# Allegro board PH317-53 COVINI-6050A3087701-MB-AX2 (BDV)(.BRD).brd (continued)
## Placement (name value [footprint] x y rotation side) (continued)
C51157  1uF_6.3V_1  [CSC_060X030X039_2]  167.38 85.8 0 top
C51158  1uF_6.3V_1  [CSC_060X030X039_2]  178.08 88.22 90 top
C51159  1uF_6.3V_1  [CSC_060X030X039_2]  173.78 89.84 0 top
C51160  1uF_6.3V_1  [CSC_060X030X039_2]  163.95 89.01 270 bottom
C51161  1uF_6.3V_1  [CSC_060X030X039_2]  177.11 85.77 180 top
C51162  1uF_6.3V_1  [CSC_060X030X039_2]  170.02 87.33 180 top
C51210  10uF_4V_3  [CSC_160X080X090_2]  183.05 85.73 270 top
C51211  10uF_4V_3  [CSC_160X080X090_2]  189.81 100.61 90 top
C51212  10uF_4V_3  [CSC_160X080X090_2]  183 100.53 90 top
C51213  10uF_4V_3  [CSC_160X080X090_2]  186.74 93.45 0 top
C51214  10uF_4V_3  [CSC_160X080X090_2]  190.55 85.55 270 top
C51215  10uF_4V_3  [CSC_160X080X090_2]  193.62 97.36 90 top
C51216  22uF_4V_3  [CSC_160X080X100_2]  188.97 83.56 0 bottom
C51217  22uF_4V_3  [CSC_160X080X100_2]  196.49 90.57 90 bottom
C51218  22uF_4V_3  [CSC_160X080X100_2]  191.89 83.56 180 bottom
C51219  22uF_4V_3  [CSC_160X080X100_2]  196.62 93.6 90 bottom
C51220  22uF_4V_3  [CSC_160X080X100_2]  184.52 83.56 180 bottom
C51221  22uF_4V_3  [CSC_160X080X100_2]  181.6 83.56 0 bottom
C51222  1uF_6.3V_1  [CSC_060X030X039_2]  191.72 85.64 180 top
C51223  1uF_6.3V_1  [CSC_060X030X039_2]  192.68 94.29 90 top
C51224  1uF_6.3V_1  [CSC_060X030X039_2]  187.7 87.33 90 top
C51225  1uF_6.3V_1  [CSC_060X030X039_2]  186.02 98.62 270 top
C51226  1uF_6.3V_1  [CSC_060X030X039_2]  181.86 85.55 0 top
C51227  1uF_6.3V_1  [CSC_060X030X039_2]  192.73 86.66 90 top
C51228  1uF_6.3V_1  [CSC_060X030X039_2]  189.2 94.95 270 top
C51229  1uF_6.3V_1  [CSC_060X030X039_2]  181.78 96.08 270 top
C51230  1uF_6.3V_1  [CSC_060X030X039_2]  183.41 93.59 0 top
C51231  1uF_6.3V_1  [CSC_060X030X039_2]  195.12 86.56 90 bottom
C51232  1uF_6.3V_1  [CSC_060X030X039_2]  184.6 90.85 180 top
C51233  1uF_6.3V_1  [CSC_060X030X039_2]  192.68 96.52 90 top
C51234  1uF_6.3V_1  [CSC_060X030X039_2]  180.85 86.67 90 top
C51235  1uF_6.3V_1  [CSC_060X030X039_2]  185.95 96.26 270 top
C51236  1uF_6.3V_1  [CSC_060X030X039_2]  188.19 96.7 180 top
C51237  1uF_6.3V_1  [CSC_060X030X039_2]  185.11 89.31 270 top
C51238  1uF_6.3V_1  [CSC_060X030X039_2]  192.68 98.93 270 top
C51239  1uF_6.3V_1  [CSC_060X030X039_2]  195.12 88.08 90 bottom
C51240  1uF_6.3V_1  [CSC_060X030X039_2]  191.74 100.41 180 top
C51241  1uF_6.3V_1  [CSC_060X030X039_2]  188.64 91.6 90 top
C51242  1uF_6.3V_1  [CSC_060X030X039_2]  192.68 89.69 90 top
C51243  1uF_6.3V_1  [CSC_060X030X039_2]  180.84 89.61 90 top
C51244  1uF_6.3V_1  [CSC_060X030X039_2]  188.51 97.91 270 top
C51245  1uF_6.3V_1  [CSC_060X030X039_2]  180.92 97.89 270 top
C51246  4.7uF_6.3V_2  [CSC_100X050X065_2]  185.08 85.13 180 top
C51247  1uF_6.3V_1  [CSC_060X030X039_2]  184.98 100.35 180 top
C51248  1uF_6.3V_1  [CSC_060X030X039_2]  185.24 85.9 180 top
C51249  1uF_6.3V_1  [CSC_060X030X039_2]  188.49 99.85 90 top
C51250  1uF_6.3V_1  [CSC_060X030X039_2]  188.67 85.68 0 top
C51251  1uF_6.3V_1  [CSC_060X030X039_2]  184.65 95.22 180 top
C51252  1uF_6.3V_1  [CSC_060X030X039_2]  195.12 89.61 90 bottom
C51253  1uF_6.3V_1  [CSC_060X030X039_2]  189.28 91.6 90 top
C51254  1uF_6.3V_1  [CSC_060X030X039_2]  180.84 90.77 270 top
C51255  1uF_6.3V_1  [CSC_060X030X039_2]  192.75 88.21 90 top
C51256  1uF_6.3V_1  [CSC_060X030X039_2]  188.49 90.15 270 top
C51257  1uF_6.3V_1  [CSC_060X030X039_2]  192.68 97.8 90 top
C51258  1uF_6.3V_1  [CSC_060X030X039_2]  181.53 99.38 270 top
C51259  1uF_6.3V_1  [CSC_060X030X039_2]  180.84 88.21 90 top
C51260  1uF_6.3V_1  [CSC_060X030X039_2]  185.14 87.74 90 top
C51261  1uF_6.3V_1  [CSC_060X030X039_2]  192.71 91.16 270 top
C51262  1uF_6.3V_1  [CSC_060X030X039_2]  181.53 94.56 180 top
C51300  22uF_4V_3  [CSC_160X080X100_2]  188.86 156.88 180 top
C51301  4.7uF_6.3V_2  [CSC_100X050X065_2]  175.95 141.52 90 top
C51302  1uF_6.3V_1  [CSC_060X030X039_2]  157.55 119 270 top
C51303  1uF_6.3V_1  [CSC_060X030X039_2]  158.16 119 270 top
C51304  1uF_6.3V_1  [CSC_060X030X039_2]  158.11 128.96 180 top
C51305  1uF_6.3V_1  [CSC_060X030X039_2]  170.18 120.58 90 top
C51306  1uF_6.3V_1  [CSC_060X030X039_2]  175.47 139.89 270 top
C51310  10pF_50V_2  [CSC_100X050X040_2]  146.99 108.06 180 bottom
C51311  10pF_50V_2  [CSC_100X050X040_2]  148.59 108.06 0 bottom
C51400  0.1uF_16V_2  [CSC_100X050X040_2]  159.28 92.66 0 bottom
C51600  4.7uF_6.3V_2  [CSC_100X050X065_2]  156.83 126.72 90 top
C51601  1uF_6.3V_1  [CSC_060X030X039_2]  158.11 125.91 0 top
C51602  1uF_6.3V_1  [CSC_060X030X039_2]  158.16 125 0 top
C51610  4.7uF_6.3V_2  [CSC_100X050X065_2]  159.84 128.63 0 top
C51611  1uF_6.3V_1  [CSC_060X030X039_2]  159.6 127.86 0 top
C51612  1uF_6.3V_1  [CSC_060X030X039_2]  158.16 124.39 0 top
C51616  1uF_6.3V_1  [CSC_060X030X039_2]  156.07 125.61 180 top
C51620  0.1uF_16V_2  [CSC_100X050X040_2]  288.06 51.44 0 top
C51621  0.1uF_16V_2  [CSC_100X050X040_2]  288.06 52.33 0 top
C51622  0.1uF_16V_2  [CSC_100X050X040_2]  288.06 53.24 0 top
C51623  0.1uF_16V_2  [CSC_100X050X040_2]  288.06 54.13 0 top
C51624  0.1uF_16V_2  [CSC_100X050X040_2]  288.06 55.05 0 top
C51625  0.1uF_16V_2  [CSC_100X050X040_2]  288.06 55.93 0 top
C51626  0.1uF_16V_2  [CSC_100X050X040_2]  288.06 56.85 0 top
C51627  0.1uF_16V_2  [CSC_100X050X040_2]  288.06 57.74 0 top
C51630  0.1uF_16V_2  [CSC_100X050X040_2]  299.92 53.22 180 top
C51631  0.1uF_16V_2  [CSC_100X050X040_2]  301.55 53.22 0 top
C51671  0.1uF_16V_2  [CSC_100X050X040_2]  297.28 62.18 180 top
C51681  0.1uF_16V_2  [CSC_100X050X040_2]  295.14 62.49 270 top
C51700  0.1uF_16V_2  [CSC_100X050X040_2]  283.18 71.5 0 top
C51701  0.1uF_16V_2  [CSC_100X050X040_2]  283.18 72.39 0 top
C51702  0.1uF_16V_2  [CSC_100X050X040_2]  283.18 73.31 0 top
C51703  0.1uF_16V_2  [CSC_100X050X040_2]  283.18 74.2 0 top
C51704  0.1uF_16V_2  [CSC_100X050X040_2]  283.56 76.69 0 top
C51705  0.1uF_16V_2  [CSC_100X050X040_2]  283.56 77.58 0 top
C51706  0.1uF_16V_2  [CSC_100X050X040_2]  283.56 78.46 0 top
C51707  0.1uF_16V_2  [CSC_100X050X040_2]  283.56 79.35 0 top
C51720  1uF_6.3V_1  [CSC_060X030X039_2]  158.16 123.78 0 top
C51730  4.7uF_6.3V_2  [CSC_100X050X065_2]  156.44 127.97 180 top
C51731  1uF_6.3V_1  [CSC_060X030X039_2]  157.58 127.94 270 top
C51732  1uF_6.3V_1  [CSC_060X030X039_2]  158.72 127.44 270 top
C51733  1uF_6.3V_1  [CSC_060X030X039_2]  158.14 126.55 0 top
C51752  1uF_6.3V_1  [CSC_060X030X039_2]  160.98 117.83 180 top
C51800  4.7uF_6.3V_2  [CSC_100X050X065_2]  159.61 126.75 90 top
C51801  1uF_6.3V_1  [CSC_060X030X039_2]  159.55 123.82 0 top
C51802  1uF_6.3V_1  [CSC_060X030X039_2]  159.55 124.42 0 top
C51803  1uF_6.3V_1  [CSC_060X030X039_2]  159.55 125.02 0 top
C51804  1uF_6.3V_1  [CSC_060X030X039_2]  159.55 125.62 0 top
C51900  1uF_6.3V_1  [CSC_060X030X039_2]  163.83 119.13 180 top
C51901  1uF_6.3V_1  [CSC_060X030X039_2]  163.83 119.76 180 top
C52000  1uF_6.3V_1  [CSC_060X030X039_2]  149.35 51.9 0 bottom
C52001  4.7uF_6.3V_2  [CSC_100X050X065_2]  161.44 115.93 0 top
C52002  4.7uF_6.3V_2  [CSC_100X050X065_2]  156.44 155.07 90 bottom
C52003  4.7uF_6.3V_2  [CSC_100X050X065_2]  147.77 145.62 180 bottom
C52004  4.7uF_6.3V_2  [CSC_100X050X065_2]  155.55 141.25 180 top
C52005  4.7uF_6.3V_2  [CSC_100X050X065_2]  158.54 145.93 0 top
C52008  CSC0402_DY  [CSC_100X050X040_2]  143.94 57.46 90 bottom
C52009  CSC0402_DY  [CSC_100X050X040_2]  143.05 57.46 90 bottom
C52010  0.015uF_50V_2  [CSC_100X050X055_2]  149.7 48.72 180 bottom
C52014  1000PF_50V_2  [CSC_100X050X055_2]  146.43 46.31 180 bottom
C52020  0.015uF_50V_2  [CSC_100X050X055_2]  141.45 45.62 90 bottom
C52024  1000PF_50V_2  [CSC_100X050X055_2]  142.72 45.27 180 bottom
C52050  100pF_50V_2  [CSC_100X050X040_2]  145.06 55.07 90 bottom
C52053  100pF_50V_2  [CSC_100X050X040_2]  147.11 55.25 90 bottom
C52055  100pF_50V_2  [CSC_100X050X040_2]  145.95 55.07 90 bottom
C52100  1uF_6.3V_1  [CSC_060X030X039_2]  159.28 91.77 180 bottom
C52101  4.7uF_6.3V_2  [CSC_100X050X065_2]  161.72 87.79 180 bottom
C52102  1uF_6.3V_1  [CSC_060X030X039_2]  157.96 121.9 270 top
C52200  3.9pF_50V_2  [CSC_100X050X050_2]  179.93 140.39 0 top
C52300  1uF_6.3V_1  [CSC_060X030X039_2]  158.16 121.03 180 top
C52301  1uF_6.3V_1  [CSC_060X030X039_2]  159.66 121.92 0 top
C52302  1uF_6.3V_1  [CSC_060X030X039_2]  159.71 121.15 0 top
C52310  4.7uF_6.3V_2  [CSC_100X050X065_2]  158.62 117.58 180 top
C52311  4.7uF_6.3V_2  [CSC_100X050X065_2]  161.26 120.6 0 top
C52312  4.7uF_6.3V_2  [CSC_100X050X065_2]  161.26 121.49 0 top
C52320  1uF_6.3V_1  [CSC_060X030X039_2]  157.88 120.02 180 top
C52321  1uF_6.3V_1  [CSC_060X030X039_2]  159.89 119.94 0 top
C52322  1uF_6.3V_1  [CSC_060X030X039_2]  159.84 118.93 0 top
C52400  1uF_6.3V_1  [CSC_060X030X039_2]  177.77 127.27 180 top
C52401  1uF_6.3V_1  [CSC_060X030X039_2]  171.47 138.84 180 top
C52402  1uF_6.3V_1  [CSC_060X030X039_2]  165.83 122.87 180 top
C52403  1uF_6.3V_1  [CSC_060X030X039_2]  172.13 134.05 0 top
C52404  1uF_6.3V_1  [CSC_060X030X039_2]  168.64 136.96 180 top
C52405  1uF_6.3V_1  [CSC_060X030X039_2]  174.95 129.21 0 top
C52406  1uF_6.3V_1  [CSC_060X030X039_2]  173.54 127.42 0 top
C52407  1uF_6.3V_1  [CSC_060X030X039_2]  173.54 129.22 180 top
C52408  1uF_6.3V_1  [CSC_060X030X039_2]  167.27 128.55 180 top
C52409  1uF_6.3V_1  [CSC_060X030X039_2]  170.05 138.15 180 top
C52410  1uF_6.3V_1  [CSC_060X030X039_2]  170.05 129.75 0 top
C52411  1uF_6.3V_1  [CSC_060X030X039_2]  174.95 137.61 0 top
C52412  1uF_6.3V_1  [CSC_060X030X039_2]  176.35 129.04 180 top
C52413  1uF_6.3V_1  [CSC_060X030X039_2]  177.77 131.47 0 top
C52414  1uF_6.3V_1  [CSC_060X030X039_2]  177.77 135.07 0 top
C52415  1uF_6.3V_1  [CSC_060X030X039_2]  171.47 138.24 0 top
C52416  1uF_6.3V_1  [CSC_060X030X039_2]  165.83 122.27 180 top
C52417  1uF_6.3V_1  [CSC_060X030X039_2]  168.64 136.36 180 top
C52418  1uF_6.3V_1  [CSC_060X030X039_2]  174.95 128.61 180 top
C52419  1uF_6.3V_1  [CSC_060X030X039_2]  173.54 126.82 180 top
C52420  1uF_6.3V_1  [CSC_060X030X039_2]  173.54 126.22 0 top
C52421  1uF_6.3V_1  [CSC_060X030X039_2]  177.77 137.47 0 top
C52422  1uF_6.3V_1  [CSC_060X030X039_2]  170.05 137.55 180 top
C52423  1uF_6.3V_1  [CSC_060X030X039_2]  170.05 129.15 0 top
C52424  1uF_6.3V_1  [CSC_060X030X039_2]  174.95 137.01 180 top
C52425  1uF_6.3V_1  [CSC_060X030X039_2]  176.35 128.44 0 top
C52426  1uF_6.3V_1  [CSC_060X030X039_2]  177.77 130.87 0 top
C52427  1uF_6.3V_1  [CSC_060X030X039_2]  177.77 134.47 0 top
C52428  1uF_6.3V_1  [CSC_060X030X039_2]  171.47 137.64 0 top
C52429  1uF_6.3V_1  [CSC_060X030X039_2]  165.86 127.94 180 top
C52430  1uF_6.3V_1  [CSC_060X030X039_2]  168.64 135.76 0 top
C52431  1uF_6.3V_1  [CSC_060X030X039_2]  174.95 128.01 0 top
C52432  1uF_6.3V_1  [CSC_060X030X039_2]  168.64 130.96 0 top
C52433  1uF_6.3V_1  [CSC_060X030X039_2]  173.54 125.62 0 top
C52434  1uF_6.3V_1  [CSC_060X030X039_2]  177.77 136.87 180 top
C52435  1uF_6.3V_1  [CSC_060X030X039_2]  170.05 136.95 0 top
C52436  1uF_6.3V_1  [CSC_060X030X039_2]  170.05 128.55 180 top
C52437  1uF_6.3V_1  [CSC_060X030X039_2]  174.95 136.41 0 top
C52438  1uF_6.3V_1  [CSC_060X030X039_2]  176.35 127.84 180 top
C52439  1uF_6.3V_1  [CSC_060X030X039_2]  177.77 130.27 180 top
C52440  1uF_6.3V_1  [CSC_060X030X039_2]  177.77 133.87 0 top
C52441  1uF_6.3V_1  [CSC_060X030X039_2]  171.47 137.04 180 top
C52442  1uF_6.3V_1  [CSC_060X030X039_2]  165.86 127.34 0 top
C52443  1uF_6.3V_1  [CSC_060X030X039_2]  168.64 135.16 0 top
C52444  1uF_6.3V_1  [CSC_060X030X039_2]  174.95 127.41 180 top
C52445  1uF_6.3V_1  [CSC_060X030X039_2]  168.64 130.36 0 top
C52446  1uF_6.3V_1  [CSC_060X030X039_2]  172.14 126.21 0 top
C52447  1uF_6.3V_1  [CSC_060X030X039_2]  167.27 127.95 0 top
C52448  1uF_6.3V_1  [CSC_060X030X039_2]  167.27 124.95 0 top
C52449  1uF_6.3V_1  [CSC_060X030X039_2]  170.05 136.35 0 top
C52450  1uF_6.3V_1  [CSC_060X030X039_2]  170.05 127.95 0 top
C52451  1uF_6.3V_1  [CSC_060X030X039_2]  174.95 135.81 180 top
C52452  1uF_6.3V_1  [CSC_060X030X039_2]  176.35 136.84 0 top
C52453  1uF_6.3V_1  [CSC_060X030X039_2]  177.77 129.67 0 top
C52454  1uF_6.3V_1  [CSC_060X030X039_2]  177.77 133.27 180 top
C52455  1uF_6.3V_1  [CSC_060X030X039_2]  172.13 136.44 0 top
C52456  1uF_6.3V_1  [CSC_060X030X039_2]  165.86 126.74 180 top
C52457  1uF_6.3V_1  [CSC_060X030X039_2]  168.64 134.56 0 top
C52458  1uF_6.3V_1  [CSC_060X030X039_2]  176.35 137.44 180 top
C52459  1uF_6.3V_1  [CSC_060X030X039_2]  174.95 129.81 0 top
C52460  1uF_6.3V_1  [CSC_060X030X039_2]  168.64 129.76 180 top
C52461  1uF_6.3V_1  [CSC_060X030X039_2]  172.14 125.61 180 top
C52462  1uF_6.3V_1  [CSC_060X030X039_2]  167.27 127.35 0 top
C52463  1uF_6.3V_1  [CSC_060X030X039_2]  170.05 135.75 0 top
C52464  1uF_6.3V_1  [CSC_060X030X039_2]  170.05 127.35 0 top
C52465  1uF_6.3V_1  [CSC_060X030X039_2]  167.27 135.82 0 top
C52466  1uF_6.3V_1  [CSC_060X030X039_2]  176.35 136.24 180 top
C52467  1uF_6.3V_1  [CSC_060X030X039_2]  177.77 129.07 0 top
C52468  1uF_6.3V_1  [CSC_060X030X039_2]  177.77 132.67 0 top
C52469  1uF_6.3V_1  [CSC_060X030X039_2]  172.13 135.85 0 top
C52470  1uF_6.3V_1  [CSC_060X030X039_2]  165.86 126.14 180 top
C52471  1uF_6.3V_1  [CSC_060X030X039_2]  176.35 124.8 0 top
C52472  1uF_6.3V_1  [CSC_060X030X039_2]  173.54 137.61 0 top
C52473  1uF_6.3V_1  [CSC_060X030X039_2]  168.64 129.16 180 top
C52474  1uF_6.3V_1  [CSC_060X030X039_2]  173.54 128.62 0 top
C52475  1uF_6.3V_1  [CSC_060X030X039_2]  167.27 126.75 0 top
C52476  1uF_6.3V_1  [CSC_060X030X039_2]  170.05 135.15 0 top
C52477  1uF_6.3V_1  [CSC_060X030X039_2]  170.05 126.75 180 top
C52478  1uF_6.3V_1  [CSC_060X030X039_2]  167.27 135.22 180 top
C52479  1uF_6.3V_1  [CSC_060X030X039_2]  176.35 135.64 0 top
C52480  1uF_6.3V_1  [CSC_060X030X039_2]  177.77 128.47 180 top
C52481  1uF_6.3V_1  [CSC_060X030X039_2]  176.35 130.84 0 top
C52482  1uF_6.3V_1  [CSC_060X030X039_2]  177.77 132.07 180 top
C52483  1uF_6.3V_1  [CSC_060X030X039_2]  172.13 135.25 180 top
C52484  1uF_6.3V_1  [CSC_060X030X039_2]  164.44 129.89 180 top
C52485  1uF_6.3V_1  [CSC_060X030X039_2]  172.13 128.05 0 top
C52486  1uF_6.3V_1  [CSC_060X030X039_2]  173.54 137.01 0 top
C52487  1uF_6.3V_1  [CSC_060X030X039_2]  168.64 128.56 0 top
C52488  1uF_6.3V_1  [CSC_060X030X039_2]  167.27 133.35 0 top
C52489  1uF_6.3V_1  [CSC_060X030X039_2]  167.27 126.15 0 top
C52490  1uF_6.3V_1  [CSC_060X030X039_2]  170.05 134.55 0 top
C52491  1uF_6.3V_1  [CSC_060X030X039_2]  170.05 126.15 0 top
C52492  1uF_6.3V_1  [CSC_060X030X039_2]  167.27 134.62 0 top
C52493  1uF_6.3V_1  [CSC_060X030X039_2]  176.35 135.04 180 top
C52494  1uF_6.3V_1  [CSC_060X030X039_2]  177.77 123.67 0 top
C52495  1uF_6.3V_1  [CSC_060X030X039_2]  177.77 127.87 0 top
C52496  1uF_6.3V_1  [CSC_060X030X039_2]  176.35 130.24 180 top
C52497  1uF_6.3V_1  [CSC_060X030X039_2]  172.13 134.65 180 top
C52498  1uF_6.3V_1  [CSC_060X030X039_2]  164.44 129.29 0 top
C52499  1uF_6.3V_1  [CSC_060X030X039_2]  173.54 128.02 180 top
C52500  1uF_6.3V_1  [CSC_060X030X039_2]  173.54 136.42 180 top
C52501  1uF_6.3V_1  [CSC_060X030X039_2]  168.64 127.96 180 top
C52502  1uF_6.3V_1  [CSC_060X030X039_2]  167.27 132.75 180 top
C52503  1uF_6.3V_1  [CSC_060X030X039_2]  167.27 125.55 0 top
C52504  1uF_6.3V_1  [CSC_060X030X039_2]  170.05 133.95 0 top
C52505  1uF_6.3V_1  [CSC_060X030X039_2]  170.05 125.55 180 top
C52506  1uF_6.3V_1  [CSC_060X030X039_2]  167.27 134.02 180 top
C52507  1uF_6.3V_1  [CSC_060X030X039_2]  176.35 134.44 180 top
C52508  1uF_6.3V_1  [CSC_060X030X039_2]  172.13 130.45 180 top
C52509  1uF_6.3V_1  [CSC_060X030X039_2]  176.35 129.64 180 top
C52510  1uF_6.3V_1  [CSC_060X030X039_2]  174.95 126.81 0 top
C52511  1uF_6.3V_1  [CSC_060X030X039_2]  164.44 124.92 0 top
C52512  1uF_6.3V_1  [CSC_060X030X039_2]  164.44 128.69 180 top
C52513  1uF_6.3V_1  [CSC_060X030X039_2]  174.95 126.2 180 top
C52514  1uF_6.3V_1  [CSC_060X030X039_2]  173.54 135.82 0 top
C52515  1uF_6.3V_1  [CSC_060X030X039_2]  168.64 127.36 0 top
C52516  1uF_6.3V_1  [CSC_060X030X039_2]  167.27 132.15 180 top
C52517  1uF_6.3V_1  [CSC_060X030X039_2]  164.44 125.53 180 top
C52518  1uF_6.3V_1  [CSC_060X030X039_2]  170.05 133.35 0 top
C52519  1uF_6.3V_1  [CSC_060X030X039_2]  170.05 124.95 180 top
C52520  1uF_6.3V_1  [CSC_060X030X039_2]  174.95 132.81 0 top
C52521  1uF_6.3V_1  [CSC_060X030X039_2]  176.35 133.84 180 top
C52522  1uF_6.3V_1  [CSC_060X030X039_2]  177.77 126.67 0 top
C52523  1uF_6.3V_1  [CSC_060X030X039_2]  173.54 129.82 180 top
C52524  1uF_6.3V_1  [CSC_060X030X039_2]  172.13 133.45 0 top
C52525  1uF_6.3V_1  [CSC_060X030X039_2]  162.35 123.54 180 top
C52526  1uF_6.3V_1  [CSC_060X030X039_2]  172.13 129.85 0 top
C52527  1uF_6.3V_1  [CSC_060X030X039_2]  173.54 135.22 0 top
C52528  1uF_6.3V_1  [CSC_060X030X039_2]  168.64 126.76 0 top
C52529  1uF_6.3V_1  [CSC_060X030X039_2]  167.27 131.55 0 top
C52530  1uF_6.3V_1  [CSC_060X030X039_2]  167.27 124.35 0 top
C52531  1uF_6.3V_1  [CSC_060X030X039_2]  170.05 132.75 180 top
C52532  1uF_6.3V_1  [CSC_060X030X039_2]  170.05 124.35 0 top
C52533  1uF_6.3V_1  [CSC_060X030X039_2]  174.95 132.21 180 top
C52534  1uF_6.3V_1  [CSC_060X030X039_2]  176.35 133.24 0 top
C52535  1uF_6.3V_1  [CSC_060X030X039_2]  177.77 126.07 180 top
C52536  1uF_6.3V_1  [CSC_060X030X039_2]  176.35 127.24 0 top
C52537  1uF_6.3V_1  [CSC_060X030X039_2]  172.13 132.85 180 top
C52538  1uF_6.3V_1  [CSC_060X030X039_2]  162.35 122.94 0 top
C52539  1uF_6.3V_1  [CSC_060X030X039_2]  172.13 129.25 0 top
C52540  1uF_6.3V_1  [CSC_060X030X039_2]  173.54 134.62 0 top
C52541  1uF_6.3V_1  [CSC_060X030X039_2]  168.64 126.16 180 top
C52542  1uF_6.3V_1  [CSC_060X030X039_2]  167.27 130.95 0 top
C52543  1uF_6.3V_1  [CSC_060X030X039_2]  167.27 123.75 0 top
C52544  1uF_6.3V_1  [CSC_060X030X039_2]  170.05 132.15 180 top
C52545  1uF_6.3V_1  [CSC_060X030X039_2]  170.05 123.75 0 top
C52546  1uF_6.3V_1  [CSC_060X030X039_2]  174.95 131.61 180 top
C52547  1uF_6.3V_1  [CSC_060X030X039_2]  176.35 132.64 180 top
C52548  1uF_6.3V_1  [CSC_060X030X039_2]  177.77 125.47 180 top
C52549  1uF_6.3V_1  [CSC_060X030X039_2]  176.35 126.64 180 top
C52550  1uF_6.3V_1  [CSC_060X030X039_2]  172.13 132.25 180 top
C52551  1uF_6.3V_1  [CSC_060X030X039_2]  162.35 122.34 180 top
C52552  1uF_6.3V_1  [CSC_060X030X039_2]  172.13 128.65 180 top
C52553  1uF_6.3V_1  [CSC_060X030X039_2]  173.54 134.02 180 top
C52554  1uF_6.3V_1  [CSC_060X030X039_2]  168.64 125.56 0 top
C52555  1uF_6.3V_1  [CSC_060X030X039_2]  167.27 130.35 180 top
C52556  1uF_6.3V_1  [CSC_060X030X039_2]  167.27 123.15 0 top
C52557  1uF_6.3V_1  [CSC_060X030X039_2]  170.05 131.55 0 top
C52558  1uF_6.3V_1  [CSC_060X030X039_2]  170.05 123.15 0 top
C52559  1uF_6.3V_1  [CSC_060X030X039_2]  174.95 131.01 180 top
C52560  1uF_6.3V_1  [CSC_060X030X039_2]  176.35 132.04 0 top
C52561  1uF_6.3V_1  [CSC_060X030X039_2]  177.77 124.87 0 top
C52562  1uF_6.3V_1  [CSC_060X030X039_2]  177.77 136.27 0 top
C52563  1uF_6.3V_1  [CSC_060X030X039_2]  172.13 131.65 0 top
C52564  1uF_6.3V_1  [CSC_060X030X039_2]  176.35 126.01 0 top
C52565  1uF_6.3V_1  [CSC_060X030X039_2]  167.27 137.02 0 top
C52566  1uF_6.3V_1  [CSC_060X030X039_2]  173.54 133.42 180 top
C52567  1uF_6.3V_1  [CSC_060X030X039_2]  168.64 124.96 0 top
C52568  1uF_6.3V_1  [CSC_060X030X039_2]  167.27 129.75 0 top
C52569  1uF_6.3V_1  [CSC_060X030X039_2]  167.27 122.55 0 top
C52570  1uF_6.3V_1  [CSC_060X030X039_2]  170.05 130.95 180 top
C52571  1uF_6.3V_1  [CSC_060X030X039_2]  170.05 122.55 0 top
C52572  1uF_6.3V_1  [CSC_060X030X039_2]  174.95 130.41 0 top
C52573  1uF_6.3V_1  [CSC_060X030X039_2]  176.35 131.44 180 top
C52574  1uF_6.3V_1  [CSC_060X030X039_2]  177.77 124.27 0 top
C52575  1uF_6.3V_1  [CSC_060X030X039_2]  177.77 135.67 180 top
C52576  1uF_6.3V_1  [CSC_060X030X039_2]  172.13 131.05 0 top
C52577  1uF_6.3V_1  [CSC_060X030X039_2]  176.35 125.4 0 top
C52578  1uF_6.3V_1  [CSC_060X030X039_2]  167.27 136.42 0 top
C52579  1uF_6.3V_1  [CSC_060X030X039_2]  173.54 132.82 180 top
C52580  1uF_6.3V_1  [CSC_060X030X039_2]  168.64 124.36 180 top
C52581  1uF_6.3V_1  [CSC_060X030X039_2]  167.27 129.15 0 top
C52582  1uF_6.3V_1  [CSC_060X030X039_2]  167.27 121.95 0 top
C52583  1uF_6.3V_1  [CSC_060X030X039_2]  170.05 130.35 180 top
C52584  1uF_6.3V_1  [CSC_060X030X039_2]  174.95 125.6 180 top
C52600  10uF_4V_3  [CSC_160X080X090_2]  161.72 131.96 0 top
C52601  10uF_4V_3  [CSC_160X080X090_2]  175.39 122.28 180 top
C52602  10uF_4V_3  [CSC_160X080X090_2]  175.39 123.6 180 top
C52603  10uF_4V_3  [CSC_160X080X090_2]  168.6 139.07 180 top
C52604  10uF_4V_3  [CSC_160X080X090_2]  162.35 126.34 270 top
C52605  10uF_4V_3  [CSC_160X080X090_2]  162.96 136.68 270 top
C52606  10uF_4V_3  [CSC_160X080X090_2]  161.67 134.9 0 top
C52607  10uF_4V_3  [CSC_160X080X090_2]  165.07 132.01 180 top
C52608  10uF_4V_3  [CSC_160X080X090_2]  165.07 133.43 180 top
C52609  10uF_4V_3  [CSC_160X080X090_2]  161.69 133.46 0 top
C52610  10uF_4V_3  [CSC_160X080X090_2]  165.07 134.8 180 top
C52611  10uF_4V_3  [CSC_160X080X090_2]  172.34 123.5 0 top
C52612  10uF_4V_3  [CSC_160X080X090_2]  172.33 122.27 0 top
C52613  10uF_4V_3  [CSC_160X080X090_2]  168.65 122.84 270 top
C52614  10uF_4V_3  [CSC_160X080X090_2]  165.88 124.46 270 top
C52615  10uF_4V_3  [CSC_160X080X090_2]  165.16 136.26 180 top
C52616  10uF_4V_3  [CSC_160X080X090_2]  163.78 122.94 270 top
C52617  10uF_4V_3  [CSC_160X080X090_2]  168.65 132.77 90 top
C52618  10uF_4V_3  [CSC_160X080X090_2]  165.88 129.44 270 top
C52619  10uF_4V_3  [CSC_160X080X090_2]  164.49 127.11 270 top
C52620  10uF_4V_3  [CSC_160X080X090_2]  174.95 134.29 90 top
C52621  10uF_4V_3  [CSC_160X080X090_2]  162.63 129.26 90 top
C52622  10uF_4V_3  [CSC_160X080X090_2]  173.53 131.32 90 top
C52630  22uF_4V_3  [CSC_160X080X100_2]  154.68 142.32 180 top
C52631  22uF_4V_3  [CSC_160X080X100_2]  155.37 150.65 0 top
C52632  22uF_4V_3  [CSC_160X080X100_2]  156.05 148.11 0 top
C52633  22uF_4V_3  [CSC_160X080X100_2]  155.37 149.43 0 top
C52640  47uF_4V_5  [CSC_200X125X145_2]  147.12 146.91 180 bottom
C52641  47uF_4V_5  [CSC_200X125X145_2]  147.12 148.56 180 bottom
C52642  47uF_4V_5  [CSC_200X125X145_2]  158.1 153.43 0 bottom
C52650  470uF_2V  [CS_730X430X190_2]  144.9 154.41 135 bottom
C52651  470uF_2V  [CS_730X430X190_2]  211.76 76.41 90 bottom
C53000  1uF_6.3V_1  [CSC_060X030X039_2]  179.83 136.45 180 top
C53001  1uF_6.3V_1  [CSC_060X030X039_2]  180.52 132.21 0 top
C53002  1uF_6.3V_1  [CSC_060X030X039_2]  180.53 133.31 0 top
C53003  1uF_6.3V_1  [CSC_060X030X039_2]  179.87 134.62 180 top
C53004  1uF_6.3V_1  [CSC_060X030X039_2]  167.46 141.11 270 top
C53005  1uF_6.3V_1  [CSC_060X030X039_2]  163.39 141.77 270 top
C53006  1uF_6.3V_1  [CSC_060X030X039_2]  162.79 141.15 270 top
C53007  1uF_6.3V_1  [CSC_060X030X039_2]  171.1 140.91 270 top
C53008  1uF_6.3V_1  [CSC_060X030X039_2]  181.35 126.14 270 top
C53009  1uF_6.3V_1  [CSC_060X030X039_2]  168.66 141.11 270 top
C53010  1uF_6.3V_1  [CSC_060X030X039_2]  168.06 141.11 270 top
C53011  1uF_6.3V_1  [CSC_060X030X039_2]  171.2 120.58 90 top
C53012  1uF_6.3V_1  [CSC_060X030X039_2]  174.42 120.73 90 top
C53013  1uF_6.3V_1  [CSC_060X030X039_2]  176 120.81 90 top
C53014  1uF_6.3V_1  [CSC_060X030X039_2]  179.24 124.3 180 top
C53015  1uF_6.3V_1  [CSC_060X030X039_2]  178.1 120.17 90 top
C53016  1uF_6.3V_1  [CSC_060X030X039_2]  176.6 120.81 90 top
C53017  1uF_6.3V_1  [CSC_060X030X039_2]  171.7 140.91 270 top
C53018  1uF_6.3V_1  [CSC_060X030X039_2]  172.3 140.91 270 top
C53019  1uF_6.3V_1  [CSC_060X030X039_2]  179.64 133.98 180 top
C53020  1uF_6.3V_1  [CSC_060X030X039_2]  179.41 132.21 180 top
C53021  1uF_6.3V_1  [CSC_060X030X039_2]  167.66 118.74 270 top
C53022  1uF_6.3V_1  [CSC_060X030X039_2]  179.29 127.78 180 top
C53023  1uF_6.3V_1  [CSC_060X030X039_2]  179.24 124.91 180 top
C53024  1uF_6.3V_1  [CSC_060X030X039_2]  166.81 120.43 90 top
C53025  1uF_6.3V_1  [CSC_060X030X039_2]  181.92 139.1 0 top
C53026  1uF_6.3V_1  [CSC_060X030X039_2]  180.59 122.58 0 top
C53027  1uF_6.3V_1  [CSC_060X030X039_2]  181.23 124.91 0 top
C53028  1uF_6.3V_1  [CSC_060X030X039_2]  181.29 130.37 0 top
C53029  1uF_6.3V_1  [CSC_060X030X039_2]  174.06 141.74 90 top
C53030  1uF_6.3V_1  [CSC_060X030X039_2]  164 141.77 270 top
C53031  1uF_6.3V_1  [CSC_060X030X039_2]  179.19 123.05 180 top
C53032  1uF_6.3V_1  [CSC_060X030X039_2]  179.83 137.06 180 top
C53033  1uF_6.3V_1  [CSC_060X030X039_2]  175.48 143.18 90 top
C53034  1uF_6.3V_1  [CSC_060X030X039_2]  181.13 138.08 0 top
C53035  1uF_6.3V_1  [CSC_060X030X039_2]  179.59 137.66 180 top
C53036  1uF_6.3V_1  [CSC_060X030X039_2]  179.84 125.55 180 top
C53037  1uF_6.3V_1  [CSC_060X030X039_2]  179.83 130.23 180 top
C53038  1uF_6.3V_1  [CSC_060X030X039_2]  179.83 129.62 180 top
C53039  1uF_6.3V_1  [CSC_060X030X039_2]  176.08 139.89 270 top
C53040  1uF_6.3V_1  [CSC_060X030X039_2]  176.68 139.89 270 top
C53041  1uF_6.3V_1  [CSC_060X030X039_2]  177.28 139.89 270 top
C53042  1uF_6.3V_1  [CSC_060X030X039_2]  173.31 140.42 270 top
C53043  1uF_6.3V_1  [CSC_060X030X039_2]  173.91 140.42 270 top
C53044  1uF_6.3V_1  [CSC_060X030X039_2]  180.71 127.78 0 top
C53045  1uF_6.3V_1  [CSC_060X030X039_2]  174.51 140.42 270 top
C53046  1uF_6.3V_1  [CSC_060X030X039_2]  178.27 139.87 270 top
C53047  1uF_6.3V_1  [CSC_060X030X039_2]  180.43 118.79 270 top
C53050  10uF_4V_3  [CSC_160X080X090_2]  178.85 122.11 180 top
C53051  10uF_4V_3  [CSC_160X080X090_2]  179.37 120.22 90 top
C53052  10uF_4V_3  [CSC_160X080X090_2]  168.04 120.48 90 top
C53053  10uF_4V_3  [CSC_160X080X090_2]  173.48 120.12 90 top
C53054  10uF_4V_3  [CSC_160X080X090_2]  172.12 120.11 90 top
C53055  10uF_4V_3  [CSC_160X080X090_2]  169.26 120.48 90 top
C53056  10uF_4V_3  [CSC_160X080X090_2]  166.54 141.1 270 top
C53057  10uF_4V_3  [CSC_160X080X090_2]  165.33 141.1 270 top
C53060  10uF_4V_3  [CSC_160X080X090_2]  179.9 135.54 180 top
C53061  10uF_4V_3  [CSC_160X080X090_2]  179.93 131.3 180 top
C53062  10uF_4V_3  [CSC_160X080X090_2]  179.9 128.71 180 top
C53063  10uF_4V_3  [CSC_160X080X090_2]  179.85 126.47 180 top
C53070  22uF_4V_3  [CSC_160X080X100_2]  203.79 91.6 90 bottom
C53071  22uF_4V_3  [CSC_160X080X100_2]  202.57 91.6 90 bottom
C53072  22uF_4V_3  [CSC_160X080X100_2]  201.32 91.6 90 bottom
C53073  22uF_4V_3  [CSC_160X080X100_2]  200.08 91.6 90 bottom
C53074  22uF_4V_3  [CSC_160X080X100_2]  193.85 172.04 90 bottom
C53075  22uF_4V_3  [CSC_160X080X100_2]  192.58 172.04 90 bottom
C53076  22uF_4V_3  [CSC_160X080X100_2]  189.43 172.42 90 bottom
C53077  22uF_4V_3  [CSC_160X080X100_2]  210.72 171.28 90 bottom
C53078  22uF_4V_3  [CSC_160X080X100_2]  209.47 171.28 90 bottom
C53500  0.1uF_16V_2  [CSC_100X050X040_2]  106.5 49.74 180 bottom
C53501  0.1uF_25V_3_DY  [CSC_160X080X080_2]  110.08 51.74 270 bottom
C53510  CSC0603_DY  [CSC_160X080X080_2]  146.15 98 270 bottom
C53520  0.1uF_16V_2  [CSC_100X050X040_2]  142.36 104.27 180 bottom
C53530  0.1uF_25V_3  [CSC_160X080X080_2]  136.29 49.1 90 bottom
C53540  0.1uF_16V_2  [CSC_100X050X040_2]  116.33 50.8 180 bottom
C53550  0.1uF_16V_2  [CSC_100X050X040_2]  103.88 55.76 90 bottom
C53552  0.1uF_25V_3  [CSC_160X080X080_2]  110.08 54.13 90 bottom
C53570  0.1uF_16V_2  [CSC_100X050X040_2]  120.8 51.24 0 bottom
C53572  0.1uF_25V_3  [CSC_160X080X080_2]  125.37 51.64 90 bottom
C53580  0.1uF_16V_2  [CSC_100X050X040_2]  117.4 59.01 180 bottom
C53582  CSC0603_DY  [CSC_160X080X080_2]  116.15 55.55 180 bottom
C53590  0.1uF_16V_2  [CSC_100X050X040_2]  120.72 50.27 180 bottom
C53592  0.1uF_25V_3  [CSC_160X080X080_2]  120.55 46.56 90 bottom
C55300  1uF_6.3V_1  [CSC_060X030X039_2]  199.44 169.93 180 top
C55301  1uF_6.3V_1  [CSC_060X030X039_2]  199.31 169.07 270 top
C55302  220pF_50V_2  [CSC_100X050X040_2]  193.75 169.32 180 top
C55303  10uF_10V_5  [CSC_200X125X140_2]  190.41 167.81 180 top
C55304  10uF_10V_5  [CSC_200X125X140_2]  190.41 166.12 180 top
C55700  0.22uF_6.3V_1  [CSC_060X030X033_2]  134.16 121.54 0 top
C55701  0.22uF_6.3V_1  [CSC_060X030X033_2]  134.16 122.15 0 top
C55702  0.22uF_6.3V_1  [CSC_060X030X033_2]  133.32 123.55 0 top
C55703  0.22uF_6.3V_1  [CSC_060X030X033_2]  133.32 122.94 0 top
C55704  0.22uF_6.3V_1  [CSC_060X030X033_2]  132.56 124.26 0 top
C55705  0.22uF_6.3V_1  [CSC_060X030X033_2]  132.56 124.87 0 top
C55706  0.22uF_6.3V_1  [CSC_060X030X033_2]  134.31 125.71 0 top
C55707  0.22uF_6.3V_1  [CSC_060X030X033_2]  134.31 125.1 0 top
C55708  0.22uF_6.3V_1  [CSC_060X030X033_2]  132.56 125.94 0 top
C55709  0.22uF_6.3V_1  [CSC_060X030X033_2]  132.56 126.55 0 top
C55710  0.22uF_6.3V_1  [CSC_060X030X033_2]  133.98 127.61 0 top
C55711  0.22uF_6.3V_1  [CSC_060X030X033_2]  133.98 127 0 top
C55712  0.22uF_6.3V_1  [CSC_060X030X033_2]  132.43 127.77 0 top
C55713  0.22uF_6.3V_1  [CSC_060X030X033_2]  132.43 128.38 0 top
C55714  0.22uF_6.3V_1  [CSC_060X030X033_2]  134.44 129.29 0 top
C55715  0.22uF_6.3V_1  [CSC_060X030X033_2]  134.44 128.68 0 top
C55716  0.22uF_6.3V_1  [CSC_060X030X033_2]  132.31 130.08 0 top
C55717  0.22uF_6.3V_1  [CSC_060X030X033_2]  132.31 129.47 0 top
C55718  0.22uF_6.3V_1  [CSC_060X030X033_2]  133.68 130.36 0 top
C55719  0.22uF_6.3V_1  [CSC_060X030X033_2]  133.68 130.97 0 top
C55720  0.22uF_6.3V_1  [CSC_060X030X033_2]  132.23 131.8 0 top
C55721  0.22uF_6.3V_1  [CSC_060X030X033_2]  132.23 131.19 0 top
C55722  0.22uF_6.3V_1  [CSC_060X030X033_2]  130.78 132.03 0 top
C55723  0.22uF_6.3V_1  [CSC_060X030X033_2]  130.78 132.64 0 top
C55724  0.22uF_6.3V_1  [CSC_060X030X033_2]  132.71 132.87 0 top
C55725  0.22uF_6.3V_1  [CSC_060X030X033_2]  132.71 133.48 0 top
C55726  0.22uF_6.3V_1  [CSC_060X030X033_2]  129.66 134.55 0 top
C55727  0.22uF_6.3V_1  [CSC_060X030X033_2]  129.66 133.94 0 top
C55728  0.22uF_6.3V_1  [CSC_060X030X033_2]  132.56 134.6 0 top
C55729  0.22uF_6.3V_1  [CSC_060X030X033_2]  132.56 135.21 0 top
C55730  0.22uF_6.3V_1  [CSC_060X030X033_2]  134.01 135.72 0 top
C55731  0.22uF_6.3V_1  [CSC_060X030X033_2]  134.01 136.33 0 top
C55800  0.1uF_16V_2  [CSC_100X050X040_2]  297.38 56.72 0 bottom
C55801  0.1uF_16V_2  [CSC_100X050X040_2]  297.38 55.83 0 bottom
C55802  0.1uF_16V_2  [CSC_100X050X040_2]  297.38 54.94 0 bottom
C55803  0.1uF_16V_2  [CSC_100X050X040_2]  297.38 54.05 0 bottom
C55804  0.1uF_16V_2  [CSC_100X050X040_2]  297.38 53.17 0 bottom
C55805  0.1uF_16V_2  [CSC_100X050X040_2]  297.38 52.28 0 bottom
C55806  0.1uF_16V_2  [CSC_100X050X040_2]  297.38 51.39 0 bottom
C55807  0.1uF_16V_2  [CSC_100X050X040_2]  297.38 50.5 0 bottom
C55820  4.7uF_6.3V_2  [CSC_100X050X065_2]  293.67 56.44 180 bottom
C55821  0.1uF_16V_2  [CSC_100X050X040_2]  293.67 57.89 180 bottom
C55822  0.1uF_16V_2  [CSC_100X050X040_2]  294.1 50.73 180 bottom
C55823  0.1uF_16V_2  [CSC_100X050X040_2]  293.8 55.15 180 bottom
C55824  0.1uF_16V_2  [CSC_100X050X040_2]  290.55 56.75 0 bottom
C55825  0.1uF_16V_2  [CSC_100X050X040_2]  290.62 55.27 0 bottom
C55826  0.1uF_16V_2  [CSC_100X050X040_2]  294.1 54.03 180 bottom
C55827  0.1uF_16V_2  [CSC_100X050X040_2]  294.1 52.61 180 bottom
C56200  0.1uF_16V_2  [CSC_100X050X040_2]  305.86 47.5 180 bottom
C56201  0.01uF_50V_2  [CSC_100X050X040_2]  305.36 48.39 180 bottom
C56202  4.7uF_6.3V_2  [CSC_100X050X065_2]  305.36 49.28 180 bottom
C56250  1uF_6.3V_1  [CSC_060X030X039_2]  294.23 37.42 0 bottom
C56251  0.01uF_50V_2  [CSC_100X050X040_2]  303.37 36.66 0 bottom
C56252  0.1uF_16V_2  [CSC_100X050X040_2]  303.37 35.72 0 bottom
C56261  220pF_50V_2  [CSC_100X050X040_2]  269.64 66.4 180 bottom
C56400  0.1uF_16V_2  [CSC_100X050X040_2]  282.42 70.11 0 top
C56402  0.1uF_16V_2  [CSC_100X050X040_2]  282.42 69.22 0 top
C56404  10uF_6.3V_3  [CSC_160X080X095_2]  293.72 79.63 270 top
C56405  4.7uF_6.3V_2  [CSC_100X050X065_2]  299.44 73.13 0 bottom
C56406  0.1uF_16V_2  [CSC_100X050X040_2]  294.41 75.09 0 top
C56407  0.1uF_16V_2  [CSC_100X050X040_2]  293.95 72.27 90 top
C56408  4.7uF_6.3V_2  [CSC_100X050X065_2]  292.81 68.61 180 top
C56409  0.1uF_16V_2  [CSC_100X050X040_2]  294.48 71 0 top
C56420  0.1uF_16V_2  [CSC_100X050X040_2]  290.75 68.81 270 top
C56421  0.1uF_16V_2  [CSC_100X050X040_2]  286.56 68.79 90 top
C56422  0.1uF_16V_2  [CSC_100X050X040_2]  283.82 68.05 90 top
C56441  4.7uF_6.3V_2  [CSC_100X050X065_2]  289.73 80.39 90 top
C56442  0.1uF_16V_2  [CSC_100X050X040_2]  291.51 80.39 90 top
C56443  0.1uF_16V_2  [CSC_100X050X040_2]  290.62 80.39 90 top
C56452  10uF_6.3V_3  [CSC_160X080X095_2]  295.5 77.96 180 top
C56610  100pF_50V_2  [CSC_100X050X040_2]  299.31 65.81 0 bottom
C56631  220pF_50V_2_DY  [CSC_100X050X040_2]  304.62 64.01 180 top
C60000  10UF_25V_5  [CSC_200X125X140_2]  49.23 31.91 270 bottom
C60001  10UF_25V_5  [CSC_200X125X140_2]  50.91 31.92 270 bottom
C60002  470pF_50V_2  [CSC_100X050X040_2]  38.58 47.89 270 bottom
C60003  0.1uF_25V_3  [CSC_160X080X080_2]  38.41 45.9 270 bottom
C60005  100pF_50V_2  [CSC_100X050X040_2]  54.68 50.09 90 bottom
C60007  100pF_50V_2  [CSC_100X050X040_2]  53.79 50.09 90 bottom
C60008  100pF_50V_2  [CSC_100X050X040_2]  197.99 44.78 270 bottom
C60009  1uF_25V_3  [CSC_160X080X080_2]  53.11 41.53 90 bottom
C60010  10UF_25V_5  [CSC_200X125X140_2]  37.89 33.17 90 bottom
C60011  10UF_25V_5  [CSC_200X125X140_2]  36.22 33.17 90 bottom
C60012  0.01uF_50V_2  [CSC_100X050X040_2]  52.42 48.47 90 bottom
C60013  0.1uF_25V_3  [CSC_160X080X080_2]  37.18 44.63 90 bottom
C60014  0.1uF_25V_3  [CSC_160X080X080_2]  50.27 44.23 90 bottom
C60015  0.047uF_16V_2  [CSC_100X050X040_2]  54.4 41.53 90 bottom
C60016  2200pF_50V_2  [CSC_100X050X040_2]  50.41 25.91 0 bottom
C60017  0.1uF_25V_3  [CSC_160X080X080_2]  50.26 41.85 270 bottom
C60018  0.1uF_16V_2  [CSC_100X050X040_2]  51.97 43.79 270 bottom
C60019  CSC0603  [CSC_160X080X080_2]  39.88 30.9 180 bottom
C60020  0.1uF_25V_3  [CSC_160X080X080_2]  62.66 45.19 90 bottom
C60021  0.1uF_16V_2  [CSC_100X050X040_2]  61.59 44.05 90 bottom
C60022  0.1uF_25V_3  [CSC_160X080X080_2]  62.66 42.85 270 bottom
C60023  2.2uF_10V_3  [CSC_160X080X080_2]  58.39 41.02 0 bottom
C60024  0.1uF_16V_2  [CSC_100X050X040_2]  59.33 42.52 270 bottom
C60025  10UF_25V_5  [CSC_200X125X140_2]  34.54 33.17 90 bottom
C60099  15uF_25V  [CS_350X280X200_2]  54.48 31.65 0 bottom
C60100  CSC_AX1.6  [CST_320X160X180_2_245]  204.45 21.53 270 top
C60101  22uF_6.3V_3  [CSC_160X080X100_2]  203.96 25.4 90 top
C60102  22uF_6.3V_3  [CSC_160X080X100_2]  205.18 25.4 90 top
C60103  22uF_6.3V_3  [CSC_160X080X100_2]  206.4 25.4 90 top
C60104  22uF_6.3V_3  [CSC_160X080X100_2]  206.57 21.8 270 top
C60109  1uF_6.3V_2  [CSC_100X050X055_2]  193.72 27.74 0 top
C60110  10UF_25V_5  [CSC_200X125X140_2]  190.27 24.77 270 top
C60111  4.7uF_25V_5  [CSC_200X125X135_2]  188.59 24.77 270 top
C60112  0.1uF_25V_2  [CSC_100X050X040_2]  191.56 24.62 270 top
C60113  15uF_25V  [CS_350X280X200_2]  186.05 23.42 270 top
C60115  0.1uF_16V_2  [CSC_100X050X040_2]  196.1 27.29 270 top
C60166  CSC0402  [CSC_100X050X040_2]  198.78 28.78 0 top
C60190  0.1uF_16V_2  [CSC_100X050X040_2]  193.34 22.28 180 top
C60191  1uF_6.3V_2  [CSC_100X050X055_2]  195.04 21.31 270 top
C60200  22UF_6.3V_5  [CSC_200X125X140_2]  256.23 24.92 90 top
C60201  22UF_6.3V_5  [CSC_200X125X140_2]  256.23 21.21 270 top
C60202  22UF_6.3V_5  [CSC_200X125X140_2]  257.91 24.92 90 top
C60203  22UF_6.3V_5  [CSC_200X125X140_2]  257.91 21.21 270 top
C60204  CSC0805  [CSC_200X125X130_2]  259.58 24.92 90 top
C60209  4.7UF_6.3V_2  [CSC_100X050X065_2]  246.91 21.34 270 top
C60210  10UF_25V_5  [CSC_200X125X140_2]  240.97 24.8 270 top
C60211  4.7uF_25V_3  [CSC_160X080X095_2]  245.03 27.77 90 top
C60212  0.1uF_25V_2  [CSC_100X050X040_2]  242.31 25.25 270 top
C60213  15uF_25V  [CS_350X280X200_2]  238.43 22.89 270 top
C60214  4.7uF_25V_3  [CSC_160X080X095_2]  243.81 27.77 90 top
C60215  0.1uF_16V_2  [CSC_100X050X040_2]  247.33 27.23 270 top
C60216  CSC0402  [CSC_100X050X040_2]  250.92 26.99 0 top
C60230  4.7UF_6.3V_2  [CSC_100X050X065_2]  246.02 21.34 270 top
C60231  1000PF_50V_2  [CSC_100X050X055_2]  243.86 20.86 0 top
C60250  100uF_6.3V  [CS_730X430X210_2]  51 82.24 90 bottom
C60251  22UF_6.3V_5  [CSC_200X125X140_2]  54.78 77.24 0 bottom
C60259  1uF_6.3V_2  [CSC_100X050X055_2]  58.21 77.63 180 bottom
C60260  4.7uF_25V_5  [CSC_200X125X135_2]  64.46 81.66 270 bottom
C60261  4.7uF_25V_5  [CSC_200X125X135_2]  62.15 84.08 90 bottom
C60262  0.1uF_25V_2  [CSC_100X050X040_2]  64.79 81.03 270 top
C60265  0.1uF_16V_2  [CSC_100X050X040_2]  59.34 84.06 180 bottom
C60266  CSC0402_DY  [CSC_100X050X040_2]  55.33 84.04 180 bottom
C60280  1uF_10V_2  [CSC_100X050X055_2]  59.28 76.2 270 bottom
C60281  470pF_50V_2  [CSC_100X050X040_2]  62.99 75.52 180 bottom
C60300  22uF_6.3V_3  [CSC_160X080X100_2]  74.32 71.23 270 bottom
C60301  22uF_6.3V_3  [CSC_160X080X100_2]  73.07 71.23 270 bottom
C60302  22uF_6.3V_3  [CSC_160X080X100_2]  71.83 71.23 270 bottom
C60303  CSC0603  [CSC_160X080X080_2]  70.58 71.23 270 bottom
C60304  CSC0603  [CSC_160X080X080_2]  69.34 71.23 270 bottom
C60309  1uF_6.3V_2  [CSC_100X050X055_2]  74.19 85.32 180 bottom
C60310  22uF_25V_5  [CSC_200X125X145_2]  71.23 86.37 0 bottom
C60311  CSC0805  [CSC_200X125X130_2]  71.23 88.05 0 bottom
C60312  0.1uF_25V_2  [CSC_100X050X040_2]  71.17 85.04 0 bottom
C60315  0.1uF_16V_2  [CSC_100X050X040_2]  67.48 78.29 270 bottom
C60316  CSC0402  [CSC_100X050X040_2]  67 75.16 0 bottom
C60348  CSC0402  [CSC_100X050X040_2]  66.11 78.59 180 bottom
C60350  22uF_6.3V_3  [CSC_160X080X100_2]  74.24 83.7 270 bottom
C60351  0.22uF_6.3V_2  [CSC_100X050X040_2]  74.57 80.93 270 bottom
C60352  CSC0603  [CSC_160X080X080_2]  75.64 80.12 270 bottom
C60400  22uF_6.3V_3  [CSC_160X080X100_2]  75.41 67.11 180 bottom
C60401  22uF_6.3V_3  [CSC_160X080X100_2]  80.84 67.11 0 bottom
C60405  22pF_50V_2  [CSC_100X050X040_2]  74.88 59.11 270 bottom
C60410  10uF_6.3V_3  [CSC_160X080X095_2]  80.22 58.84 90 bottom
C60500  22uF_6.3V_3  [CSC_160X080X100_2]  79.57 108.61 0 bottom
C60501  22uF_6.3V_3  [CSC_160X080X100_2]  73.69 109.94 180 bottom
C60502  22uF_6.3V_3  [CSC_160X080X100_2]  73.69 111.19 180 bottom
C60509  1uF_6.3V_2  [CSC_100X050X055_2]  68.8 102.71 180 bottom
C60510  10UF_25V_5  [CSC_200X125X140_2]  65.17 105.83 90 bottom
C60511  0.1uF_25V_2  [CSC_100X050X040_2]  66.46 105.78 90 bottom
C60515  0.1uF_16V_2  [CSC_100X050X040_2]  71.55 101.83 0 bottom
C60516  CSC0402  [CSC_100X050X040_2]  75.54 101.83 0 bottom
C60600  10uF_6.3V_3  [CSC_160X080X095_2]  220.21 26.01 180 top
C60605  330pF_50V_2  [CSC_100X050X040_2]  212.88 21.74 0 top
C60610  4.7uF_6.3V_3  [CSC_160X080X090_2]  214.86 24.77 0 top
C60900  22UF_6.3V_3  [CSC_160X080X090_2]  231.31 54.38 0 bottom
C60901  22UF_6.3V_3  [CSC_160X080X090_2]  231.31 55.6 0 bottom
C60902  22UF_6.3V_3  [CSC_160X080X090_2]  231.31 56.82 0 bottom
C60903  22UF_6.3V_3  [CSC_160X080X090_2]  231.31 58.04 0 bottom
C60904  CSC0603  [CSC_160X080X080_2]  231.31 59.26 0 bottom
C60909  4.7UF_6.3V_2  [CSC_100X050X065_2]  221.86 54.47 90 bottom
C60910  10UF_25V_5  [CSC_200X125X140_2]  224.2 47.58 180 bottom
C60911  CSC0805  [CSC_200X125X130_2]  226.89 50.84 0 bottom
C60912  0.1uF_25V_2  [CSC_100X050X040_2]  223.96 48.9 180 bottom
C60915  0.1uF_16V_2  [CSC_100X050X040_2]  226.55 53.29 180 bottom
C60916  CSC0402  [CSC_100X050X040_2]  225.84 61.27 0 bottom
C60920  220pF_50V_2  [CSC_100X050X040_2]  220.07 53.56 270 bottom
C60930  1uF_10V_2  [CSC_100X050X055_2]  220.97 54.47 90 bottom
C66000  330uF_2V_9mR_Pana_-35%  [CS_730X430X210_2]  99.06 151.13 180 bottom
C66001  330uF_2V_9mR_Pana_-35%  [CS_730X430X210_2]  119.78 151.13 180 bottom
C66002  CSC_DX1.9  [CS_730X430X190_2]  131.52 151.13 0 bottom
C66003  22uF_6.3V_3  [CSC_160X080X100_2]  95.93 154.41 180 bottom
C66004  CSC_DX1.9  [CS_730X430X190_2]  110.64 151.13 0 bottom
C66006  22uF_6.3V_3  [CSC_160X080X100_2]  113.74 154.38 0 bottom
C66007  22uF_6.3V_3  [CSC_160X080X100_2]  116.68 154.38 180 bottom
C66008  CSC0603  [CSC_160X080X080_2]  134.54 154.38 0 bottom
C66009  CSC0603  [CSC_160X080X080_2]  101.29 148.03 180 bottom
C66010  10uF_25V_5  [CSC_200X125X190_2]  103.19 171.16 270 bottom
C66011  4.7uF_25V_3  [CSC_160X080X095_2]  104.64 170.89 270 bottom
C66015  0.22uF_16V_2  [CSC_100X050X055_2]  100.68 174.86 270 bottom
C66016  1000PF_50V_2  [CSC_100X050X055_2]  100.66 168.23 0 top
C66017  2.2UF_6.3V_2  [CSC_100X050X055_2]  95.63 171.12 270 bottom
C66018  1uF_6.3V_2  [CSC_100X050X055_2]  98.65 174.87 90 bottom
C66020  10uF_25V_5  [CSC_200X125X190_2]  113.5 171.22 270 bottom
C66021  4.7uF_25V_3  [CSC_160X080X095_2]  114.96 170.95 270 bottom
C66025  0.22uF_16V_2  [CSC_100X050X055_2]  111.05 174.91 270 bottom
C66026  1000PF_50V_2  [CSC_100X050X055_2]  111.12 168.23 0 top
C66027  2.2UF_6.3V_2  [CSC_100X050X055_2]  106.34 171.09 270 bottom
C66028  1uF_6.3V_2  [CSC_100X050X055_2]  109.01 174.91 90 bottom
C66030  10uF_25V_5  [CSC_200X125X190_2]  123.91 171.2 270 bottom
C66031  4.7uF_25V_3  [CSC_160X080X095_2]  125.37 170.92 270 bottom
C66035  0.22uF_16V_2  [CSC_100X050X055_2]  121.46 174.88 270 bottom
C66036  1000PF_50V_2  [CSC_100X050X055_2]  121.56 168.23 0 top
C66037  2.2UF_6.3V_2  [CSC_100X050X055_2]  116.76 170.88 270 bottom
C66038  1uF_6.3V_2  [CSC_100X050X055_2]  119.42 174.9 90 bottom
C66040  10uF_25V_5  [CSC_200X125X190_2]  134.29 171.25 270 bottom
C66041  4.7uF_25V_3  [CSC_160X080X095_2]  135.73 170.97 270 bottom
C66045  0.22uF_16V_2  [CSC_100X050X055_2]  131.82 174.91 270 bottom
C66046  1000PF_50V_2  [CSC_100X050X055_2]  131.98 168.28 0 top
C66047  2.2UF_6.3V_2  [CSC_100X050X055_2]  127.13 170.91 270 bottom
C66048  1uF_6.3V_2  [CSC_100X050X055_2]  129.78 174.91 90 bottom
C66100  1uF_10V_2  [CSC_100X050X055_2]  82.52 157.28 90 top
C66107  470pF_50V_2  [CSC_100X050X040_2]  88.24 163.04 90 top
C66109  1uF_10V_2  [CSC_100X050X055_2]  85.14 171.02 90 top
C66113  0.01uF_50V_2  [CSC_100X050X040_2]  90.45 167.82 0 top
C66114  0.047uF_25V_2  [CSC_100X050X040_2]  88.8 168.17 90 top
C66124  0.047uF_25V_2  [CSC_100X050X040_2]  88.49 169.77 270 top
C66134  0.047uF_25V_2  [CSC_100X050X040_2]  89.02 171.02 180 top
C66144  0.047uF_25V_2  [CSC_100X050X040_2]  79.42 170.64 0 top
C66150  1000PF_50V_2  [CSC_100X050X055_2]  88.69 166.55 90 top
C66151  CSC0402  [CSC_100X050X040_2]  89.58 166.55 90 top
C66160  0.1uF_16V_2  [CSC_100X050X040_2]  87.25 169.52 270 top
C66170  270pF_50V  [CSC_100X050X055_2]  91.54 162.25 180 top
C66171  3300pF_50V_2  [CSC_100X050X040_2]  91.72 164.06 180 top
C66172  47pF_50V_2  [CSC_100X050X040_2]  90.4 164.46 270 top
C66180  1000PF_50V_2  [CSC_100X050X055_2]  90.83 161.01 90 top
C66182  1000PF_50V_2  [CSC_100X050X055_2]  88.29 161.44 270 top
C66197  CSC0402  [CSC_100X050X040_2]  81.48 170.61 0 top
C66198  CSC0402  [CSC_100X050X040_2]  83.49 172.09 180 top
C66199  0.01uF_50V_2  [CSC_100X050X040_2]  86.03 170.76 90 top
C66296  15uF_25V  [CS_350X280X200_2]  134.29 177.5 90 bottom
C66297  15uF_25V  [CS_350X280X200_2]  123.92 177.5 90 bottom
C66298  15uF_25V  [CS_350X280X200_2]  113.48 177.5 90 bottom
C66299  15uF_25V  [CS_350X280X200_2]  103.63 176.97 90 bottom
C66300  CSC_DX1.9  [CS_730X430X190_2]  76.15 124.95 90 bottom
C66301  330uF_2V_9mR_Pana_-35%  [CS_730X430X210_2]  89.94 151.84 90 bottom
C66303  22uF_6.3V_3  [CSC_160X080X100_2]  78.99 130.15 180 bottom
C66306  22uF_6.3V_3  [CSC_160X080X100_2]  79 131.39 180 bottom
C66307  22uF_6.3V_3  [CSC_160X080X100_2]  79 132.62 180 bottom
C66308  22uF_6.3V_3  [CSC_160X080X100_2]  76.53 125.43 90 bottom
C66309  22uF_6.3V_3  [CSC_160X080X100_2]  77.75 125.43 90 bottom
C66310  4.7uF_25V_3  [CSC_160X080X095_2]  77.68 142.68 315 bottom
C66311  4.7uF_25V_3  [CSC_160X080X095_2]  78.55 143.56 315 bottom
C66312  1UF_25V_2  [CSC_100X050X055_2]  79.4 144.21 315 bottom
C66315  0.22uF_16V_2  [CSC_100X050X055_2]  78.02 146.05 135 bottom
C66316  1000PF_50V_2  [CSC_100X050X055_2]  65.76 128.5 270 bottom
C66317  1uF_25V_3  [CSC_160X080X080_2]  81.54 145.8 225 bottom
C66407  470pF_50V_2  [CSC_100X050X040_2]  80.19 163.93 0 bottom
C66413  0.01uF_50V_2  [CSC_100X050X040_2]  78.38 168.3 90 top
C66414  0.047uF_25V_2  [CSC_100X050X040_2]  76.55 170.15 270 top
C66450  1200pF_50V_2  [CSC_100X050X040_2]  77.11 166.7 90 top
C66451  CSC0402  [CSC_100X050X040_2]  76.22 166.7 90 top
C66460  0.1uF_16V_2  [CSC_100X050X040_2]  79.63 170.33 270 bottom
C66470  270pF_50V  [CSC_100X050X055_2]  77.24 162.64 180 top
C66471  3300pF_50V_2  [CSC_100X050X040_2]  75.64 163.71 180 top
C66472  47pF_50V_2  [CSC_100X050X040_2]  77.44 164.79 90 top
C66480  1000PF_50V_2  [CSC_100X050X055_2]  77.9 160.15 180 top
C66482  1000PF_50V_2  [CSC_100X050X055_2]  78.36 161.39 270 top
C66598  15uF_25V  [CS_350X280X200_2]  76.33 148.77 45 bottom
C66599  15uF_25V  [CS_350X280X200_2]  68.45 141.28 135 bottom
C66600  22uF_6.3V_3  [CSC_160X080X100_2]  137.69 159.19 180 bottom
C66601  22uF_6.3V_3  [CSC_160X080X100_2]  137.69 157.97 180 bottom
C66602  22uF_6.3V_3  [CSC_160X080X100_2]  137.69 156.75 180 bottom
C66603  CSC0603  [CSC_160X080X080_2]  141.42 159.19 0 bottom
C66604  CSC0603  [CSC_160X080X080_2]  137.69 155.53 180 bottom
C66605  1000PF_50V_2  [CSC_100X050X055_2]  85.52 162.28 270 bottom
C66607  470pF_50V_2  [CSC_100X050X040_2]  83.74 162.28 90 bottom
C66610  10uF_25V_5  [CSC_200X125X190_2]  140.31 175.37 0 bottom
C66611  10uF_25V_5  [CSC_200X125X190_2]  140.31 177.04 0 bottom
C66615  0.1uF_16V_2  [CSC_100X050X040_2]  145.25 169.86 180 bottom
C66616  CSC0402  [CSC_100X050X040_2]  141.5 173.71 90 top
C66617  2.2UF_6.3V_2  [CSC_100X050X055_2]  143.66 165.23 270 bottom
C66650  6800pF_25V_2  [CSC_100X050X040_2]  84.91 157.43 180 top
C66651  0.033uF_16V_2  [CSC_100X050X040_2]  84.91 158.32 180 top
C66652  2200pF_50V_2  [CSC_100X050X040_2]  84.91 160.1 180 top
C66670  0.01uF_50V_2  [CSC_100X050X040_2]  86.15 157.83 270 top
C66671  47pF_50V_2  [CSC_100X050X040_2]  86.51 159.08 0 top
C66680  1000PF_50V_2  [CSC_100X050X055_2]  90.32 158.62 90 top
C66682  1000PF_50V_2  [CSC_100X050X055_2]  89.08 158.34 180 top
C66683  1000PF_50V_2  [CSC_100X050X055_2]  88.49 159.59 90 top
C67000  330uF_2V_9mR_Pana_-35%  [CS_730X430X210_2]  172.56 76.58 90 bottom
C67001  330uF_2V_9mR_Pana_-35%  [CS_730X430X210_2]  167.76 76.58 90 bottom
C67002  330uF_2V_9mR_Pana_-35%  [CS_730X430X210_2]  184.91 78.42 0 bottom
C67003  330uF_2V_9mR_Pana_-35%  [CS_730X430X210_2]  184.91 73.69 0 bottom
C67004  330uF_2V_9mR_Pana_-35%  [CS_730X430X210_2]  194.21 73.71 180 bottom
C67005  330uF_2V_9mR_Pana_-35%  [CS_730X430X210_2]  207.09 76.42 90 bottom
C67006  330uF_2V_9mR_Pana_-35%  [CS_730X430X210_2]  194.23 78.43 180 bottom
C67009  1uF_6.3V_2  [CSC_100X050X040_2]  136.28 59.14 0 top
C67010  10uF_25V_5  [CSC_200X125X190_2]  161.18 52.57 0 bottom
C67011  10uF_25V_5  [CSC_200X125X190_2]  161.18 50.89 0 bottom
C67012  1uF_25V_3  [CSC_160X080X080_2]  158.92 58.59 180 bottom
C67013  15uF_25V  [CS_350X280X200_2]  165.71 50.94 90 bottom
C67015  0.22uF_16V_2  [CSC_100X050X055_2]  157.07 58.04 90 bottom
C67016  CSC0402  [CSC_100X050X040_2]  165.57 57.62 180 bottom
C67019  1uF_6.3V_2  [CSC_100X050X055_2]  158.15 56.49 270 bottom
C67020  10uF_25V_5  [CSC_200X125X190_2]  171.08 52.57 0 bottom
C67021  10uF_25V_5  [CSC_200X125X190_2]  171.08 50.89 0 bottom
C67022  1uF_25V_3  [CSC_160X080X080_2]  168.9 58.59 180 bottom
C67023  15uF_25V  [CS_350X280X200_2]  175.59 50.93 90 bottom
C67025  0.22uF_16V_2  [CSC_100X050X055_2]  167.01 58.04 90 bottom
C67026  CSC0402  [CSC_100X050X040_2]  175.52 57.65 180 bottom
C67029  1uF_6.3V_2  [CSC_100X050X055_2]  168.08 56.48 270 bottom
C67030  10uF_25V_5  [CSC_200X125X190_2]  181.06 52.61 0 bottom
C67031  10uF_25V_5  [CSC_200X125X190_2]  181.06 50.94 0 bottom
C67032  1uF_25V_3  [CSC_160X080X080_2]  178.88 58.6 180 bottom
C67033  15uF_25V  [CS_350X280X200_2]  185.49 51 90 bottom
C67035  0.22uF_16V_2  [CSC_100X050X055_2]  176.97 58.07 90 bottom
C67036  CSC0402  [CSC_100X050X040_2]  185.54 57.63 180 bottom
C67039  1uF_6.3V_2  [CSC_100X050X055_2]  178.04 56.53 270 bottom
C67040  10uF_25V_5  [CSC_200X125X190_2]  191.05 52.66 0 bottom
C67041  10uF_25V_5  [CSC_200X125X190_2]  191.05 50.96 0 bottom
C67042  1uF_25V_3  [CSC_160X080X080_2]  188.89 58.6 180 bottom
C67043  15uF_25V  [CS_350X280X200_2]  195.6 51 90 bottom
C67045  0.22uF_16V_2  [CSC_100X050X055_2]  186.95 58.12 90 bottom
C67046  CSC0402  [CSC_100X050X040_2]  195.57 57.63 180 bottom
C67049  1uF_6.3V_2  [CSC_100X050X055_2]  188.02 56.61 270 bottom
C67050  10uF_25V_5  [CSC_200X125X190_2]  201.11 52.64 0 bottom
C67051  10uF_25V_5  [CSC_200X125X190_2]  201.11 50.96 0 bottom
C67052  1uF_25V_3  [CSC_160X080X080_2]  198.9 58.62 180 bottom
C67053  15uF_25V  [CS_350X280X200_2]  205.64 50.97 90 bottom
C67055  0.22uF_16V_2  [CSC_100X050X055_2]  196.99 58.09 90 bottom
C67056  CSC0402  [CSC_100X050X040_2]  205.53 57.63 180 bottom
C67059  1uF_6.3V_2  [CSC_100X050X055_2]  198.08 56.51 270 bottom
C67060  10uF_25V_5  [CSC_200X125X190_2]  211.06 52.61 0 bottom
C67061  10uF_25V_5  [CSC_200X125X190_2]  211.05 50.94 0 bottom
C67062  1uF_25V_3  [CSC_160X080X080_2]  208.88 58.6 180 bottom
C67063  15uF_25V  [CS_350X280X200_2]  215.67 50.98 90 bottom
C67065  0.22uF_16V_2  [CSC_100X050X055_2]  207.02 58.12 90 bottom
C67066  CSC0402  [CSC_100X050X040_2]  215.56 57.63 180 bottom
C67069  1uF_6.3V_2  [CSC_100X050X055_2]  208.09 56.53 270 bottom
C67080  CSC0402  [CSC_100X050X040_2]  127 52.76 90 top
C67081  CSC0402  [CSC_100X050X040_2]  132.41 48.72 0 top
C67082  0.01uF_50V_2  [CSC_100X050X040_2]  137.92 51.39 90 top
C67087  1000PF_50V_2  [CSC_100X050X055_2]  128.01 58.88 90 top
C67088  1uF_6.3V_2  [CSC_100X050X040_2]  127.75 56.61 180 top
C67089  1000PF_50V_2  [CSC_100X050X055_2]  128.26 54.8 180 top
C67090  22UF_6.3V_3  [CSC_160X080X090_2]  175.56 80.24 90 bottom
C67091  22UF_6.3V_3  [CSC_160X080X090_2]  176.78 80.24 90 bottom
C67092  22UF_6.3V_3  [CSC_160X080X090_2]  178.28 80.24 90 bottom
C67093  22UF_6.3V_3  [CSC_160X080X090_2]  179.5 80.24 90 bottom
C67094  22UF_6.3V_3  [CSC_160X080X090_2]  199.89 80.39 90 bottom
C67095  22UF_6.3V_3  [CSC_160X080X090_2]  201.11 80.39 90 bottom
C67096  22UF_6.3V_3  [CSC_160X080X090_2]  204.16 80.39 90 bottom
C67097  CSC0603  [CSC_160X080X080_2]  202.94 80.39 90 bottom
C67200  330uF_2V_9mR_Pana_-35%  [CS_730X430X210_2]  225.36 78.17 270 bottom
C67201  330uF_2V_9mR_Pana_-35%  [CS_730X430X210_2]  209.13 85.53 270 bottom
C67202  22UF_6.3V_3  [CSC_160X080X090_2]  230.03 84.13 90 bottom
C67203  22UF_6.3V_3  [CSC_160X080X090_2]  228.79 84.13 90 bottom
C67204  22UF_6.3V_3  [CSC_160X080X090_2]  227.54 84.13 90 bottom
C67209  2.2UF_6.3V_3  [CSC_160X080X090_2]  235.91 77.24 180 bottom
